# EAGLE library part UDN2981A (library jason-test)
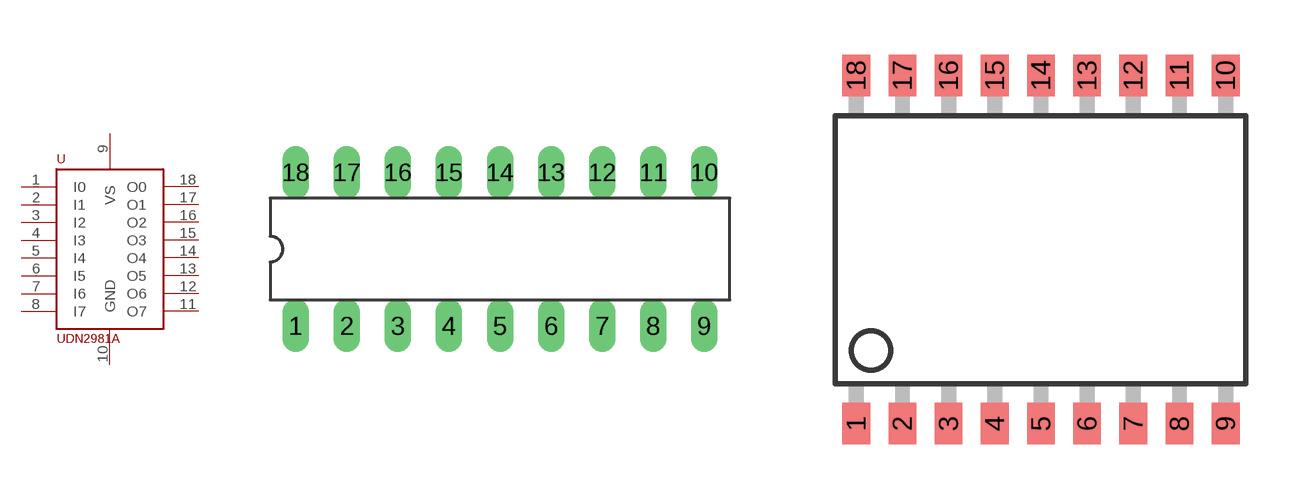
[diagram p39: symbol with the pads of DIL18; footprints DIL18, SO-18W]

Designator prefix -

## UDN2981AD  [DIL18]
1  I0  in
2  I1  in
3  I2  in
4  I3  in
5  I4  in
6  I5  in
7  I6  in
8  I7  in
9  VS  pwr
10  GND  pwr
11  O7  out
12  O6  out
13  O5  out
14  O4  out
15  O3  out
16  O2  out
17  O1  out
18  O0  out

## UDN2981AS  [SO-18W]
Pads as for DIL18

## Footprint DIL18 (pad centres in mm)
Dual In Line package type P
drill 0.813 long: 1 -10.16,-3.81; 2 -7.62,-3.81; 3 -5.08,-3.81; 4 -2.54,-3.81; 5 0,-3.81; 6 2.54,-3.81; 7 5.08,-3.81; 8 7.62,-3.81; 9 10.16,-3.81; 10 10.16,3.81; 11 7.62,3.81; 12 5.08,3.81; 13 2.54,3.81; 14 0,3.81; 15 -2.54,3.81; 16 -5.08,3.81; 17 -7.62,3.81; 18 -10.16,3.81

## Footprint SO-18W (pad centres in mm)
Small Outline Wide Plastic Gull Wing 300-mil body, package type SO
smd 0.762 x 1.143: 1 -5.08,-4.788; 2 -3.81,-4.788; 3 -2.54,-4.788; 4 -1.27,-4.788; 5 0,-4.788; 6 1.27,-4.788; 7 2.54,-4.788; 8 3.81,-4.788; 9 5.08,-4.788; 10 5.08,4.788; 11 3.81,4.788; 12 2.54,4.788; 13 1.27,4.788; 14 0,4.788; 15 -1.27,4.788; 16 -2.54,4.788; 17 -3.81,4.788; 18 -5.08,4.788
